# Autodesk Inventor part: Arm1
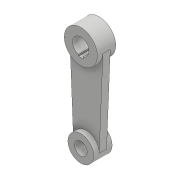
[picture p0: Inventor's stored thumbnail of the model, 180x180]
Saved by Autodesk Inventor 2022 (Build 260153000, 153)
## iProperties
Created: 2016-05
Part Number: Arm1
Material: Generic
Document SubType Name: Modeling
Designer: CADCIM
Density: 1 g/cm^3
Appearance: Default
Author: CADCIM
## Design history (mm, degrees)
sketch "Sketch1"
  geometry: C1 r 56.25 at (0, 0); C2 r 28 at (0, 0); C3 r 43.75 at (0, -300); C4 r 21.75 at (0, -300); 1 further point
  constraints: 4 centre point, 3 coincident
  dimensions: "d0" = 112.5 diameter of C1; "d1" = 56 diameter of C2; "d2" = 87.5 diameter of C3; "d3" = 43.5 diameter of C4; "d4" = 300 distance of C4.centre C2.centre
extrude "Extrusion1" new body sketch "Sketch1" stored distance "d5" = 62.5; taper "d6" = 0 deg
sketch "Sketch2"
  geometry: L1 (56.201, -2.344)-(43.712, -301.823); L2 (-56.201, -2.344)-(-43.712, -301.823); A1 r 56.25 centre (0, 0) between (-56.201, -2.344) and (56.201, -2.344); A2 r 43.75 centre (0, -300) between (43.712, -301.823) and (-43.712, -301.823); 3 further points
  constraints: 4 end point, 4 point on circle, 2 centre point, 2 coincident
extrude "Extrusion2" join sketch "Sketch2" stored distance "d7" = 25; taper "d8" = 0 deg
sketch "Sketch3"
  geometry: L1 (0, 0)-(0, 99.622); L2 (-8, 26.833)-(8, 26.833); L3 (8, 26.833)-(8, 32.3); L4 (8, 32.3)-(-8, 32.3); L5 (-8, 32.3)-(-8, 26.833); L6 (0, 0)-(0, -28); A1 r 28 centre (0, 0) between (-8, 26.833) and (8, 26.833) reference
  constraints: 12 end point, 3 point on circle, 2 parallel, 2 vertical, 1 horizontal, 1 perpendicular, 1 other
  dimensions: "d10" = 16 distance of L3.end L4.end; "d11" = 60.3 distance from line of L4 L6.end
extrude "Extrusion3" cut sketch "Sketch3" extent not by distance; stored distance "d12" = 25; taper "d13" = 0 deg
fillet "Fillet1" dims "d14" = 0.4
body "Solid1"
